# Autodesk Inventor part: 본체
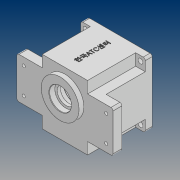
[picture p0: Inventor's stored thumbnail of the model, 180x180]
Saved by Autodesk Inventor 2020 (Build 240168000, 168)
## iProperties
Created: 2020-07
Part Number: 본체
Material: 일반
Document SubType Name: Modeling
Designer: PC312-
Mass: 324.553 g
Surface Area: 794.057 cm^2
Volume: 324.553 cm^3
Density: 1 g/cm^3
Appearance: 기본값
Author: PC312-
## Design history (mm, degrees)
sketch "스케치1"
  geometry: L1 (-47, -47)-(47, -47); L2 (47, -47)-(47, 47); L3 (47, 47)-(-47, 47); L4 (-47, 47)-(-47, -47); L5 (-47, -47)-(47, 47); L6 (47, -47)-(-47, 47); 1 further point
  constraints: 12 end point, 2 midpoint, 2 parallel, 1 horizontal, 1 perpendicular
  dimensions: "d0" = 94 distance of L3.end L2.end; "d1" = 94 distance of L2.end L1.end
extrude "돌출1" new body sketch "스케치1" distance "d2" = 10; taper "d3" = 0 deg
sketch "스케치2"
  geometry: L1 (-47, -30)-(47, -30); L2 (47, -30)-(47, 30); L3 (47, 30)-(-47, 30); L4 (-47, 30)-(-47, -30); L5 (-47, -30)-(47, 30); L6 (47, -30)-(-47, 30); L7 (-33, -47)-(33, -47); L8 (33, -47)-(33, 47); L9 (33, 47)-(-33, 47); L10 (-33, 47)-(-33, -47); L11 (-33, -47)-(33, 47); L12 (33, -47)-(-33, 47); 5 further points
  constraints: 24 end point, 4 midpoint, 4 parallel, 2 horizontal, 2 perpendicular
  dimensions: "d4" = 94 distance of L3.end L2.end; "d5" = 60 distance of L2.end L1.end; "d6" = 66 distance of L9.end L8.end; "d7" = 94 distance of L8.end L7.end
extrude "돌출2" join sketch "스케치2" distance "d8" = 70; taper "d9" = 0 deg
sketch "스케치3"
  geometry: C1 r 27.5 at (0, 11); 1 further point
  constraints: 1 centre point, 1 vertical alignment
  dimensions: "d10" = 55 diameter of C1; "d11" = 11 distance of point (0, 0) C1.centre
extrude "돌출3" join sketch "스케치3" distance "d12" = 7; taper "d13" = 0 deg
sketch "스케치4"
  geometry: C1 r 27.5 at (0, 0) reference; C2 r 16 at (0, 0); 1 further point
  constraints: 1 centre point, 1 coincident
  dimensions: "d14" = 32 diameter of C2
extrude "돌출4" cut sketch "스케치4" distance "d15" = 8.3; taper "d16" = 0 deg
sketch "스케치5"
  geometry: C1 r 16 at (0, 0) reference; C2 r 12.5 at (0, 0); 1 further point
  constraints: 1 centre point, 1 coincident
  dimensions: "d17" = 25 diameter of C2
extrude "돌출5" cut sketch "스케치5" distance "d18" = 4.7; taper "d19" = 0 deg
sketch "스케치6"
  geometry: C1 r 12.5 at (0, 0) reference; C2 r 17.5 at (0, 0); 1 further point
  constraints: 1 centre point, 1 coincident
  dimensions: "d20" = 35 diameter of C2
extrude "돌출6" cut sketch "스케치6" distance "d21" = 10; taper "d22" = 0 deg
sketch "스케치7"
  geometry: L1 (-70, -30)-(70, -30); L2 (70, -30)-(70, 30); L3 (70, 30)-(-70, 30); L4 (-70, 30)-(-70, -30); L5 (-70, -30)-(70, 30); L6 (70, -30)-(-70, 30); L7 (-47, 30)-(-47, -30) reference; L8 (47, -30)-(47, 30) reference; 1 further point
  constraints: 12 end point, 2 midpoint, 2 parallel, 1 horizontal, 1 perpendicular
  dimensions: "d23" = 140 distance of L3.end L2.end; "d24" = 60 distance of L2.end L1.end
extrude "돌출7" join sketch "스케치7" distance "d25" = 13; taper "d26" = 0 deg
sketch "스케치8"
  geometry: C1 r 43 at (0, 0); 1 further point
  constraints: 1 centre point, 1 coincident
  dimensions: "d27" = 86 diameter of C1
extrude "돌출8" cut sketch "스케치8" distance "d28" = 9; taper "d29" = 0 deg
sketch "스케치9"
  geometry: C1 r 40 at (0, 0); 1 further point
  constraints: 1 centre point, 1 coincident
  dimensions: "d30" = 80 diameter of C1
extrude "돌출9" cut sketch "스케치9" distance "d31" = 55; taper "d32" = 0 deg
sketch "스케치10"
  geometry: C1 r 11 at (0, -20); 1 further point
  constraints: 1 centre point, 1 vertical alignment
  dimensions: "d33" = 22 diameter of C1; "d34" = 20 distance of point (0, 0) C1.centre
extrude "돌출10" cut sketch "스케치10" distance "d35" = 7; taper "d36" = 0 deg
sketch "스케치11"
  geometry: C1 r 11 at (0, 0) reference; C2 r 9.5 at (0, 0); 1 further point
  constraints: 1 centre point, 1 coincident
  dimensions: "d37" = 19 diameter of C2
extrude "돌출11" cut sketch "스케치11" distance "d38" = 3; taper "d39" = 0 deg
sketch "스케치12"
  geometry: C1 r 16 at (0, 11) reference; C2 r 11 at (0, -20) reference; C3 r 40 at (0, 0) reference; A1 r 21 centre (0, 11) between (8.978, -7.984) and (-8.978, -7.984); A2 r 15 centre (0, -20) between (-8.978, -7.984) and (8.978, -7.984); 1 further point
  constraints: 4 point on circle, 2 centre point, 2 coincident
  dimensions: "d40" = 42 diameter of A1; "d41" = 30 diameter of A2
extrude "돌출12" cut sketch "스케치12" distance "d42" = 7; taper "d43" = 0 deg
sketch "스케치16"
  geometry: A1 r 4 centre (-36, 0) between (-36.19, -3.995) and (-36.19, 3.995); A2 r 36 centre (0, 0) between (-36, 0) and (-35.772, 4.045); A3 r 3 centre (-36.333, 6.992) between (-39.279, 7.559) and (-35.772, 4.045); A4 r 40 centre (0, 0) between (-39.279, 7.559) and (-39.279, -7.559) reference; A5 r 3 centre (-36.333, -6.992) between (-35.772, -4.045) and (-39.279, -7.559); 1 further point
  constraints: 13 point on circle, 4 centre point, 4 tangent, 1 coincident, 1 horizontal alignment
  dimensions: "d44" = 8 diameter of A1; "d45" = 72 diameter of A2; "d47" = 6 diameter of A3; "d48" = 6 diameter of A5
extrude "돌출13" join sketch "스케치16" stored distance "d49" = 7; taper "d50" = 0 deg
sketch "스케치17"
  geometry: A1 r 4 centre (-36, 0) between (-36.19, -3.995) and (-36.19, 3.995) reference; 2 further points
  constraints: 1 coincident
hole "구멍1" sketch "스케치17" at (-36, 0) diameter "d51" = 3.45873; stored, may be unused: countersink angle "d55" = 90 deg, drill point angle "d57" = 118 deg; dims "d52" = 7, "d53" = 4, "d54" = 2, "d56" = 9
sketch "스케치18"
  geometry: L1 (-70, 30)-(-70, -30) reference; 3 further points
  dimensions: "d58" = 38 distance of point (-60, -19) point (-60, 19); "d59" = 19 vertical distance of point (0, 0) point (-60, 19); "d60" = 10 distance from line of L1 point (-60, -19); "d61" = 10 distance from line of L1 point (-60, 19)
hole "구멍2" sketch "스케치18" at (-60, 19), (-60, -19) diameter "d62" = 4.5; stored, may be unused: countersink angle "d66" = 90 deg, drill point angle "d68" = 118 deg; dims "d63" = 7, "d64" = 4, "d65" = 2, "d67" = 9
sketch "스케치19"
  geometry: C1 r 2.25 at (60, 19) reference; C2 r 2.25 at (60, -19) reference; 3 further points
  constraints: 2 coincident
hole "구멍3" sketch "스케치19" at (60, 19), (60, -19) diameter "d69" = 10; stored, may be unused: countersink angle "d73" = 90 deg, drill point angle "d75" = 0 deg; dims "d70" = 7, "d71" = 4, "d72" = 2, "d74" = 5
sketch "스케치20"
  geometry: C1 r 3.5 at (40, 40); 1 further point
  constraints: 1 centre point
  dimensions: "d76" = 7 diameter of C1; "d77" = 40 horizontal distance of point (0, 0) C1.centre; "d78" = 40 horizontal distance of point (0, 0) C1.centre
extrude "돌출14" cut sketch "스케치20" extent not by distance; stored distance "d79" = 0; taper "d80" = 0 deg
fillet "모깎기1" dims "d87" = 3
fillet "모깎기2" dims "d88" = 3
chamfer "모따기1" distance "d89" = 1; stored, may be unused: second distance "d90" = 2, angle "d91" = 45 deg
chamfer "모따기2" distance "d92" = 0.8; stored, may be unused: second distance "d93" = 2, angle "d94" = 30 deg
node "작업 평면1"
sketch "스케치21"
  geometry: L1 (80, 70)-(80, 13) reference; L2 (77, 80)-(-11, 80) reference; 3 further points
  constraints: 1 midpoint, 1 vertical alignment, 1 other
  dimensions: "d97" = 40 distance from line of L2 point (33, 40)
feature "엠보싱1" sketch "스케치21" dims "d0" = 94, "d1" = 94, "d98" = 0.5, "d99" = 0
node "솔리드1"
mirror "미러1"
mirror "미러2"
pattern_linear "직사각형 패턴1" dims "d83" = 80, "d86" = 80
feature "A9D066F2-1C7D-4E18-AEED-F7BC21143FA4" dims "d62" = 4.5, "d63" = 7, "d64" = 4, "d65" = 2, "d66" = 90 deg, "d67" = 9, "d68" = 118 deg
